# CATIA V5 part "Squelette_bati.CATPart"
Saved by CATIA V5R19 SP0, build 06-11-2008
Part number: Squelette_bati
Bounding box of the stored display mesh (mm): x -500 to 500, y -2391.774 to 0, z -1458.497 to 2248.181
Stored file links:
  C:\Users\Guillaume et Fanny\Documents\IFMA\2A\IAO\Squelette_bati.CATPart
  C:\Users\Guillaume et Fanny\Documents\IFMA\2A\IAO\Train d'aterrissage.CATProduct
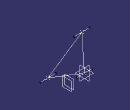
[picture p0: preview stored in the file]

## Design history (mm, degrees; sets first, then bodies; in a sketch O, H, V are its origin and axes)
Set1
  Point1 to Point3: linked copy from another document
Body1 (main body)
  Line1: type PtDir, Direction (1, 0, 0), Start -500, End 500, RefPoint Point1
  Line2: type PtDir, Direction (1, 0, 0), Start -500, End 500, RefPoint Point2
  Line3: type PtDir, Direction (1, 0, 0), Start -500, End 500, RefPoint Point3
  Line4: type PtPt, SecondPoint Point1, FirstPoint Point3
  Line5: type PtPt, SecondPoint Point2, FirstPoint Point3
  Line6: type PtPt, SecondPoint Point2, FirstPoint Point1
  Plane1: type Offset, Offset 1000, RefPlane yz-plane
  Plane2 "Plan.1170": type Offset, Offset 1170, RefPlane yz-plane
